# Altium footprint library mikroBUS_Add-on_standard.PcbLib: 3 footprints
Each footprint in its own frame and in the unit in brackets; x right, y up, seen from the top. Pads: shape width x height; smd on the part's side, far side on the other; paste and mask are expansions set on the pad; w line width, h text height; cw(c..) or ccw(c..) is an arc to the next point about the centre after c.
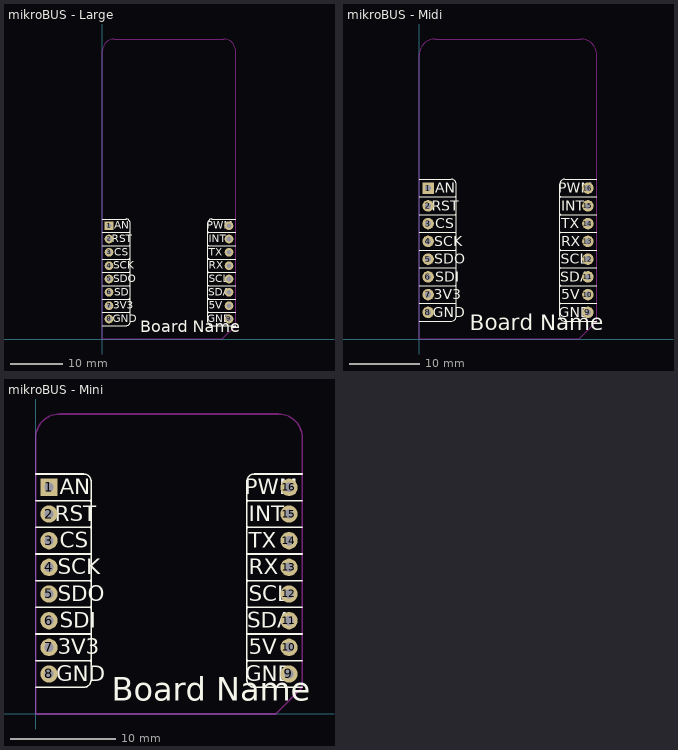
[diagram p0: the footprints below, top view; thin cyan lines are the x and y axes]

## mikroBUS - Large [mil]
height 47.24
pads (16):
  rect 65x65 hole 35: 1(50,850)
  round 65 hole 35: 2(50,750) 3(50,650) 4(50,550) 5(50,450) 6(50,350) 7(50,250) 8(50,150) 9(950,150) 10(950,250) 11(950,350) 12(950,450) 13(950,550) 14(950,650) 15(950,750) 16(950,850)
Top Overlay:
  lines w6: 0,100 180.05,100 ; 0,900 180,900 cw(c180,872.05) 207.95,872.05 ; 180.05,100.05 ccw(c180.05,128) 208,128 208,872.05 ; 208,805 cw(c203,805) 203,800 ; 792,805 ccw(c797,805) 797,800 ; 792,872.05 792,128 ccw(c819.95,128) 819.95,100.05 ; 792.05,872.05 cw(c820,872.05) 820,900 1000,900 ; 819.95,100 1000,100 ; 203,200 cw(c203,195) 208,195 ccw(c203,195) 203,200 ; 203,200 ccw(c203,205) 208,205 208,295 ; 203,200 0,200 203,200 ; 203,300 cw(c203,295) 208,295 ; 203,300 ccw(c203,305) 208,305 208,395 ; 203,300 cw(c203,295) 208,295 ; 203,300 0,300 203,300 ; 203,400 cw(c203,395) 208,395 ; 203,400 ccw(c203,405) 208,405 208,495 ; 203,400 cw(c203,395) 208,395 ; 203,400 0,400 203,400 ; 203,500 cw(c203,495) 208,495 ; 203,500 ccw(c203,505) 208,505 208,595 ; 203,500 cw(c203,495) 208,495 ; 203,500 0,500 203,500 ; 203,600 cw(c203,595) 208,595 ; 203,600 ccw(c203,605) 208,605 208,695 ; 203,600 cw(c203,595) 208,595 ; 203,600 0,600 203,600 ; 203,700 cw(c203,695) 208,695 ; 203,700 ccw(c203,705) 208,705 208,795 ; 203,700 cw(c203,695) 208,695 ; 203,700 0,700 203,700 ; 203,800 cw(c203,795) 208,795 ; 203,800 cw(c203,795) 208,795 ; 203,800 0,800 203,800 ; 792,295 cw(c797,295) 797,300 ; 792,295 cw(c797,295) 797,300 ; 792,295 792,205 ccw(c797,205) 797,200 ; 792,395 cw(c797,395) 797,400 ; 792,395 cw(c797,395) 797,400 ; 792,395 792,305 ccw(c797,305) 797,300 ; 792,495 cw(c797,495) 797,500 ; 792,495 cw(c797,495) 797,500 ; 792,495 792,405 ccw(c797,405) 797,400 ; 792,595 cw(c797,595) 797,600 ; 792,595 cw(c797,595) 797,600 ; 792,595 792,505 ccw(c797,505) 797,500 ; 792,695 cw(c797,695) 797,700 ; 792,695 cw(c797,695) 797,700 ; 792,695 792,605 ccw(c797,605) 797,600 ; 792,795 cw(c797,795) 797,800 ; 792,795 cw(c797,795) 797,800 ; 792,795 792,705 ccw(c797,705) 797,700 ; 797,200 ccw(c797,195) 792,195 cw(c797,195) 797,200 ; 797,200 1000,200 797,200 ; 797,300 1000,300 797,300 ; 797,400 1000,400 797,400 ; 797,500 1000,500 797,500 ; 797,600 1000,600 797,600 ; 797,700 1000,700 797,700 ; 797,800 1000,800 797,800
  text "RST" at 71.17,703 h100
  text "CS" at 90,603 h100
  text "SCK" at 83.67,503 h100
  text "SDO" at 83.46,403 h100
  text "SDI" at 90,303 h100
  text "3V3" at 82.43,203 h100
  text "GND" at 76.8,103 h100
  text "AN" at 90,803 h100
  text "GND" at 786.59,103 h100
  text "5V" at 799.79,203 h100
  text "SDA" at 793.76,303 h100
  text "SCL" at 798.39,403 h100
  text "RX" at 799.79,503 h100
  text "TX" at 799.79,603 h100
  text "INT" at 799.79,703 h100
  text "PWM" at 784,803 h100
  text "Board Name" at 285,19 h150
Bottom Overlay:
  lines w6: 0,100 221.05,100 ; 0,900 221,900 cw(c221,872.05) 248.95,872.05 248.95,128.05 ; 221.05,100.05 ccw(c221.05,128) 249,128 ; 249,128.05 249,195 ccw(c244,195) 244,200 ; 249,805 cw(c244,805) 244,800 ; 751,128 ccw(c778.95,128) 778.95,100.05 ; 751,128.05 751,195 cw(c756,195) 756,200 ; 751,805 ccw(c756,805) 756,800 ; 751.05,128.05 751.05,872.05 cw(c779,872.05) 779,900 1000,900 ; 778.95,100 1000,100 ; 244,200 ccw(c244,205) 249,205 249,295 ccw(c244,295) 244,300 ; 244,200 0,200 244,200 ; 244,300 ccw(c244,305) 249,305 249,395 ccw(c244,395) 244,400 ; 244,300 0,300 244,300 ; 244,400 ccw(c244,405) 249,405 249,495 ccw(c244,495) 244,500 ; 244,400 0,400 244,400 ; 244,500 ccw(c244,505) 249,505 249,595 ccw(c244,595) 244,600 ; 244,500 0,500 244,500 ; 244,600 ccw(c244,605) 249,605 249,695 ccw(c244,695) 244,700 ; 244,600 0,600 244,600 ; 244,700 ccw(c244,705) 249,705 249,795 ccw(c244,795) 244,800 ; 244,700 0,700 244,700 ; 244,800 0,800 244,800 ; 756,200 cw(c756,205) 751,205 751,295 cw(c756,295) 756,300 ; 756,200 1000,200 756,200 ; 756,300 cw(c756,305) 751,305 751,395 cw(c756,395) 756,400 ; 756,300 1000,300 756,300 ; 756,400 cw(c756,405) 751,405 751,495 cw(c756,495) 756,500 ; 756,400 1000,400 756,400 ; 756,500 cw(c756,505) 751,505 751,595 cw(c756,595) 756,600 ; 756,500 1000,500 756,500 ; 756,600 cw(c756,605) 751,605 751,695 cw(c756,695) 756,700 ; 756,600 1000,600 756,600 ; 756,700 cw(c756,705) 751,705 751,795 cw(c756,795) 756,800 ; 756,700 1000,700 756,700 ; 756,800 1000,800 756,800
  text "AN" at 230,803 h110
  text "GND" at 243.2,103 h110
  text "3V3" at 237.57,203 h110
  text "SDI" at 230,303 h110
  text "SDO" at 230,403 h110
  text "SCK" at 230,503 h110
  text "CS" at 230,603 h110
  text "RST" at 248.83,703 h110
  text "GND" at 898.55,103 h110
  text "5V" at 885.35,203 h110
  text "SDA" at 885.35,303 h110
  text "SCL" at 885.35,403 h110
  text "RX" at 885.35,503 h110
  text "TX" at 885.35,603 h110
  text "INT" at 885.35,703 h110
  text "PWM" at 890,803 h110
Keep-Out Layer:
  lines w6: 0,0 900,0 1000,100 1000,2160 ccw(c910,2160) 910,2250 90,2250 ccw(c90,2160) 0,2160 0,0
3D body "Header 1x8.stp": height 81.88, standoff -398.04, extent -5,100 109.96,900
3D body "Header 1x8.stp": height 81.88, standoff -398.04, extent 895,100 1009.96,900

## mikroBUS - Midi [mil]
height 47.24
pads (16):
  rect 65x65 hole 35: 1(50,850)
  round 65 hole 35: 2(50,750) 3(50,650) 4(50,550) 5(50,450) 6(50,350) 7(50,250) 8(50,150) 9(950,150) 10(950,250) 11(950,350) 12(950,450) 13(950,550) 14(950,650) 15(950,750) 16(950,850)
Top Overlay:
  lines w6: 0,100 180.05,100 ; 0,900 180,900 cw(c180,872.05) 207.95,872.05 ; 180.05,100.05 ccw(c180.05,128) 208,128 208,872.05 ; 208,805 cw(c203,805) 203,800 ; 792,805 ccw(c797,805) 797,800 ; 792,872.05 792,128 ccw(c819.95,128) 819.95,100.05 ; 792.05,872.05 cw(c820,872.05) 820,900 1000,900 ; 819.95,100 1000,100 ; 203,200 cw(c203,195) 208,195 ccw(c203,195) 203,200 ; 203,200 ccw(c203,205) 208,205 208,295 ; 203,200 0,200 203,200 ; 203,300 cw(c203,295) 208,295 ; 203,300 ccw(c203,305) 208,305 208,395 ; 203,300 cw(c203,295) 208,295 ; 203,300 0,300 203,300 ; 203,400 cw(c203,395) 208,395 ; 203,400 ccw(c203,405) 208,405 208,495 ; 203,400 cw(c203,395) 208,395 ; 203,400 0,400 203,400 ; 203,500 cw(c203,495) 208,495 ; 203,500 ccw(c203,505) 208,505 208,595 ; 203,500 cw(c203,495) 208,495 ; 203,500 0,500 203,500 ; 203,600 cw(c203,595) 208,595 ; 203,600 ccw(c203,605) 208,605 208,695 ; 203,600 cw(c203,595) 208,595 ; 203,600 0,600 203,600 ; 203,700 cw(c203,695) 208,695 ; 203,700 ccw(c203,705) 208,705 208,795 ; 203,700 cw(c203,695) 208,695 ; 203,700 0,700 203,700 ; 203,800 cw(c203,795) 208,795 ; 203,800 cw(c203,795) 208,795 ; 203,800 0,800 203,800 ; 792,295 cw(c797,295) 797,300 ; 792,295 cw(c797,295) 797,300 ; 792,295 792,205 ccw(c797,205) 797,200 ; 792,395 cw(c797,395) 797,400 ; 792,395 cw(c797,395) 797,400 ; 792,395 792,305 ccw(c797,305) 797,300 ; 792,495 cw(c797,495) 797,500 ; 792,495 cw(c797,495) 797,500 ; 792,495 792,405 ccw(c797,405) 797,400 ; 792,595 cw(c797,595) 797,600 ; 792,595 cw(c797,595) 797,600 ; 792,595 792,505 ccw(c797,505) 797,500 ; 792,695 cw(c797,695) 797,700 ; 792,695 cw(c797,695) 797,700 ; 792,695 792,605 ccw(c797,605) 797,600 ; 792,795 cw(c797,795) 797,800 ; 792,795 cw(c797,795) 797,800 ; 792,795 792,705 ccw(c797,705) 797,700 ; 797,200 ccw(c797,195) 792,195 cw(c797,195) 797,200 ; 797,200 1000,200 797,200 ; 797,300 1000,300 797,300 ; 797,400 1000,400 797,400 ; 797,500 1000,500 797,500 ; 797,600 1000,600 797,600 ; 797,700 1000,700 797,700 ; 797,800 1000,800 797,800
  text "Board Name" at 285,19 h150
  text "PWM" at 784,803 h100
  text "INT" at 799.79,703 h100
  text "TX" at 799.79,603 h100
  text "RX" at 799.79,503 h100
  text "SCL" at 798.39,403 h100
  text "SDA" at 793.76,303 h100
  text "5V" at 799.79,203 h100
  text "GND" at 786.59,103 h100
  text "AN" at 90,803 h100
  text "GND" at 76.8,103 h100
  text "3V3" at 82.43,203 h100
  text "SDI" at 90,303 h100
  text "SDO" at 83.46,403 h100
  text "SCK" at 83.67,503 h100
  text "CS" at 90,603 h100
  text "RST" at 71.17,703 h100
Bottom Overlay:
  lines w6: 0,100 221.05,100 ; 0,900 221,900 cw(c221,872.05) 248.95,872.05 248.95,128.05 ; 221.05,100.05 ccw(c221.05,128) 249,128 ; 249,128.05 249,195 ccw(c244,195) 244,200 ; 249,805 cw(c244,805) 244,800 ; 751,128 ccw(c778.95,128) 778.95,100.05 ; 751,128.05 751,195 cw(c756,195) 756,200 ; 751,805 ccw(c756,805) 756,800 ; 751.05,128.05 751.05,872.05 cw(c779,872.05) 779,900 1000,900 ; 778.95,100 1000,100 ; 244,200 ccw(c244,205) 249,205 249,295 ccw(c244,295) 244,300 ; 244,200 0,200 244,200 ; 244,300 ccw(c244,305) 249,305 249,395 ccw(c244,395) 244,400 ; 244,300 0,300 244,300 ; 244,400 ccw(c244,405) 249,405 249,495 ccw(c244,495) 244,500 ; 244,400 0,400 244,400 ; 244,500 ccw(c244,505) 249,505 249,595 ccw(c244,595) 244,600 ; 244,500 0,500 244,500 ; 244,600 ccw(c244,605) 249,605 249,695 ccw(c244,695) 244,700 ; 244,600 0,600 244,600 ; 244,700 ccw(c244,705) 249,705 249,795 ccw(c244,795) 244,800 ; 244,700 0,700 244,700 ; 244,800 0,800 244,800 ; 756,200 cw(c756,205) 751,205 751,295 cw(c756,295) 756,300 ; 756,200 1000,200 756,200 ; 756,300 cw(c756,305) 751,305 751,395 cw(c756,395) 756,400 ; 756,300 1000,300 756,300 ; 756,400 cw(c756,405) 751,405 751,495 cw(c756,495) 756,500 ; 756,400 1000,400 756,400 ; 756,500 cw(c756,505) 751,505 751,595 cw(c756,595) 756,600 ; 756,500 1000,500 756,500 ; 756,600 cw(c756,605) 751,605 751,695 cw(c756,695) 756,700 ; 756,600 1000,600 756,600 ; 756,700 cw(c756,705) 751,705 751,795 cw(c756,795) 756,800 ; 756,700 1000,700 756,700 ; 756,800 1000,800 756,800
  text "PWM" at 890,803 h110
  text "INT" at 885.35,703 h110
  text "TX" at 885.35,603 h110
  text "RX" at 885.35,503 h110
  text "SCL" at 885.35,403 h110
  text "SDA" at 885.35,303 h110
  text "5V" at 885.35,203 h110
  text "GND" at 898.55,103 h110
  text "RST" at 248.83,703 h110
  text "CS" at 230,603 h110
  text "SCK" at 230,503 h110
  text "SDO" at 230,403 h110
  text "SDI" at 230,303 h110
  text "3V3" at 237.57,203 h110
  text "GND" at 243.2,103 h110
  text "AN" at 230,803 h110
Keep-Out Layer:
  lines w6: 0,0 0,1600 cw(c90,1600) 90,1690 910,1690 cw(c910,1600) 1000,1600 1000,100 900,0 0,0
3D body "Header 1x8.stp": height 81.88, standoff -398.04, extent 895,100 1009.96,900
3D body "Header 1x8.stp": height 81.88, standoff -398.04, extent -5,100 109.96,900

## mikroBUS - Mini [mil]
height 47.24
pads (16):
  rect 65x65 hole 35: 1(50,850)
  round 65 hole 35: 2(50,750) 3(50,650) 4(50,550) 5(50,450) 6(50,350) 7(50,250) 8(50,150) 9(950,150) 10(950,250) 11(950,350) 12(950,450) 13(950,550) 14(950,650) 15(950,750) 16(950,850)
Top Overlay:
  lines w6: 0,100 180.05,100 ; 0,900 180,900 cw(c180,872.05) 207.95,872.05 ; 180.05,100.05 ccw(c180.05,128) 208,128 208,872.05 ; 208,805 cw(c203,805) 203,800 ; 792,805 ccw(c797,805) 797,800 ; 792,872.05 792,128 ccw(c819.95,128) 819.95,100.05 ; 792.05,872.05 cw(c820,872.05) 820,900 1000,900 ; 819.95,100 1000,100 ; 203,200 cw(c203,195) 208,195 ccw(c203,195) 203,200 ; 203,200 ccw(c203,205) 208,205 208,295 ; 203,200 0,200 203,200 ; 203,300 cw(c203,295) 208,295 ; 203,300 ccw(c203,305) 208,305 208,395 ; 203,300 cw(c203,295) 208,295 ; 203,300 0,300 203,300 ; 203,400 cw(c203,395) 208,395 ; 203,400 ccw(c203,405) 208,405 208,495 ; 203,400 cw(c203,395) 208,395 ; 203,400 0,400 203,400 ; 203,500 cw(c203,495) 208,495 ; 203,500 ccw(c203,505) 208,505 208,595 ; 203,500 cw(c203,495) 208,495 ; 203,500 0,500 203,500 ; 203,600 cw(c203,595) 208,595 ; 203,600 ccw(c203,605) 208,605 208,695 ; 203,600 cw(c203,595) 208,595 ; 203,600 0,600 203,600 ; 203,700 cw(c203,695) 208,695 ; 203,700 ccw(c203,705) 208,705 208,795 ; 203,700 cw(c203,695) 208,695 ; 203,700 0,700 203,700 ; 203,800 cw(c203,795) 208,795 ; 203,800 cw(c203,795) 208,795 ; 203,800 0,800 203,800 ; 792,295 cw(c797,295) 797,300 ; 792,295 cw(c797,295) 797,300 ; 792,295 792,205 ccw(c797,205) 797,200 ; 792,395 cw(c797,395) 797,400 ; 792,395 cw(c797,395) 797,400 ; 792,395 792,305 ccw(c797,305) 797,300 ; 792,495 cw(c797,495) 797,500 ; 792,495 cw(c797,495) 797,500 ; 792,495 792,405 ccw(c797,405) 797,400 ; 792,595 cw(c797,595) 797,600 ; 792,595 cw(c797,595) 797,600 ; 792,595 792,505 ccw(c797,505) 797,500 ; 792,695 cw(c797,695) 797,700 ; 792,695 cw(c797,695) 797,700 ; 792,695 792,605 ccw(c797,605) 797,600 ; 792,795 cw(c797,795) 797,800 ; 792,795 cw(c797,795) 797,800 ; 792,795 792,705 ccw(c797,705) 797,700 ; 797,200 ccw(c797,195) 792,195 cw(c797,195) 797,200 ; 797,200 1000,200 797,200 ; 797,300 1000,300 797,300 ; 797,400 1000,400 797,400 ; 797,500 1000,500 797,500 ; 797,600 1000,600 797,600 ; 797,700 1000,700 797,700 ; 797,800 1000,800 797,800
  text "Board Name" at 285,19 h150
  text "PWM" at 784,803 h100
  text "INT" at 799.79,703 h100
  text "TX" at 799.79,603 h100
  text "RX" at 799.79,503 h100
  text "SCL" at 798.39,403 h100
  text "SDA" at 793.76,303 h100
  text "5V" at 799.79,203 h100
  text "GND" at 786.59,103 h100
  text "AN" at 90,803 h100
  text "GND" at 76.8,103 h100
  text "3V3" at 82.43,203 h100
  text "SDI" at 90,303 h100
  text "SDO" at 83.46,403 h100
  text "SCK" at 83.67,503 h100
  text "CS" at 90,603 h100
  text "RST" at 71.17,703 h100
Bottom Overlay:
  lines w6: 0,100 221.05,100 ; 0,900 221,900 cw(c221,872.05) 248.95,872.05 248.95,128.05 ; 221.05,100.05 ccw(c221.05,128) 249,128 ; 249,128.05 249,195 ccw(c244,195) 244,200 ; 249,805 cw(c244,805) 244,800 ; 751,128 ccw(c778.95,128) 778.95,100.05 ; 751,128.05 751,195 cw(c756,195) 756,200 ; 751,805 ccw(c756,805) 756,800 ; 751.05,128.05 751.05,872.05 cw(c779,872.05) 779,900 1000,900 ; 778.95,100 1000,100 ; 244,200 ccw(c244,205) 249,205 249,295 ccw(c244,295) 244,300 ; 244,200 0,200 244,200 ; 244,300 ccw(c244,305) 249,305 249,395 ccw(c244,395) 244,400 ; 244,300 0,300 244,300 ; 244,400 ccw(c244,405) 249,405 249,495 ccw(c244,495) 244,500 ; 244,400 0,400 244,400 ; 244,500 ccw(c244,505) 249,505 249,595 ccw(c244,595) 244,600 ; 244,500 0,500 244,500 ; 244,600 ccw(c244,605) 249,605 249,695 ccw(c244,695) 244,700 ; 244,600 0,600 244,600 ; 244,700 ccw(c244,705) 249,705 249,795 ccw(c244,795) 244,800 ; 244,700 0,700 244,700 ; 244,800 0,800 244,800 ; 756,200 cw(c756,205) 751,205 751,295 cw(c756,295) 756,300 ; 756,200 1000,200 756,200 ; 756,300 cw(c756,305) 751,305 751,395 cw(c756,395) 756,400 ; 756,300 1000,300 756,300 ; 756,400 cw(c756,405) 751,405 751,495 cw(c756,495) 756,500 ; 756,400 1000,400 756,400 ; 756,500 cw(c756,505) 751,505 751,595 cw(c756,595) 756,600 ; 756,500 1000,500 756,500 ; 756,600 cw(c756,605) 751,605 751,695 cw(c756,695) 756,700 ; 756,600 1000,600 756,600 ; 756,700 cw(c756,705) 751,705 751,795 cw(c756,795) 756,800 ; 756,700 1000,700 756,700 ; 756,800 1000,800 756,800
  text "PWM" at 890,803 h110
  text "INT" at 885.35,703 h110
  text "TX" at 885.35,603 h110
  text "RX" at 885.35,503 h110
  text "SCL" at 885.35,403 h110
  text "SDA" at 885.35,303 h110
  text "5V" at 885.35,203 h110
  text "GND" at 898.55,103 h110
  text "RST" at 248.83,703 h110
  text "CS" at 230,603 h110
  text "SCK" at 230,503 h110
  text "SDO" at 230,403 h110
  text "SDI" at 230,303 h110
  text "3V3" at 237.57,203 h110
  text "GND" at 243.2,103 h110
  text "AN" at 230,803 h110
Keep-Out Layer:
  lines w6: 0,0 0,1035 cw(c90,1035) 90,1125 910,1125 cw(c910,1035) 1000,1035 1000,100 900,0 0,0
3D body "Header 1x8.stp": height 81.88, standoff -398.04, extent 895,100 1009.96,900
3D body "Header 1x8.stp": height 81.88, standoff -398.04, extent -5,100 109.96,900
